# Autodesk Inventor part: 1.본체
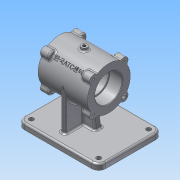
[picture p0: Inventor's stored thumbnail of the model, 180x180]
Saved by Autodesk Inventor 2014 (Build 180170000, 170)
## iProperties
Created: 2016-01
Part Number: 1.본체
Material: 알루미늄 6061
Document SubType Name: Modeling
Designer: Administrator
Density: 2.71 g/cm^3
Appearance: 알루미늄 - 평지
Mass: 1060.55 g
Surface Area: 842.535 cm^2
Volume: 391.348 cm^3
Author: Administrator
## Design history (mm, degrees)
sketch "스케치1"
  geometry: L1 (-70, 55)-(70, 55); L2 (70, 55)-(70, -55); L3 (70, -55)-(-70, -55); L4 (-70, -55)-(-70, 55); L5 (-70, 55)-(70, -55); L6 (70, 55)-(-70, -55); 1 further point
  constraints: 12 end point, 2 midpoint, 2 parallel, 1 horizontal, 1 perpendicular
  dimensions: "d0" = 140 distance between parallel lines of L2 L4; "d1" = 110 distance between parallel lines of L3 L1
extrude "돌출1" new body sketch "스케치1" distance "d2" = 10; taper "d3" = 0 deg
node "작업 평면1"
sketch "스케치2"
  geometry: L1 (0, 110)-(0, 0) reference; C1 r 37 at (-80, 55); 2 further points
  constraints: 1 centre point, 1 horizontal alignment, 1 midpoint
  dimensions: "d5" = 80 distance from line of L1 C1.centre; "d6" = 74 diameter of C1
extrude "돌출2" join sketch "스케치2" stored distance "d7" = 85; taper "d8" = 0 deg
node "작업 평면2"
sketch "스케치3"
  geometry: L1 (80, -55)-(80, 55) reference; L2 (80, -55)-(70, -55) reference; L3 (70, 55)-(70, -55) reference; L4 (80, 55)-(70, 55) reference; L5 (0, -37)-(70, -37); L6 (0, 37)-(70, 37); A1 r 37 centre (0, 0) between (0, -37) and (0, 37) reference; 1 further point
  constraints: 4 end point, 2 horizontal, 2 point on circle, 2 point on line, 2 tangent
extrude "돌출3" join sketch "스케치3" stored distance "d10" = 8; taper "d11" = 0 deg
node "작업 평면3"
sketch "스케치4"
  geometry: L1 (-70, 0)-(70, 0) reference; L2 (-70, 0)-(-70, 10) reference; L3 (70, 10)-(-70, 10) reference; L4 (70, 0)-(70, 10) reference; L5 (14, 80)-(14, 80) reference; L6 (14, 80)-(6, 80) reference; L7 (6, 80)-(6, 80) reference; L8 (14, 80)-(6, 80) reference; L9 (52.5, 43)-(52.5, 117) reference; L10 (-32.5, 117)-(-32.5, 43) reference; L11 (-9.782, 42.948)-(-15, 10); L12 (29.782, 42.948)-(35, 10); L13 (6, 10)-(14, 10) reference; L14 (6, 80)-(6, 10) reference; L15 (14, 80)-(6, 80) reference; L16 (14, 10)-(14, 80) reference; L17 (-9.782, 42.948)-(-6.179, 65.693); L18 (29.782, 42.948)-(26.179, 65.693); L19 (26.179, 65.693)-(-6.179, 65.693); 3 further points
  constraints: 10 end point, 2 collinear, 2 midpoint, 2 point on line, 1 equal length, 1 horizontal, 1 vertical alignment
  dimensions: "d13" = 99 deg angle of L3 L11; "d14" = 99 deg angle of L3 L12; "d18" = 25 distance of point (10, 10) L11.end; "d19" = 25 distance of point (10, 10) L12.end; "d20" = 32.35825 distance of L18.end L17.end
extrude "돌출4" join sketch "스케치4" stored distance "d21" = 12; taper "d22" = 0 deg
node "작업 평면4"
sketch "스케치6"
  geometry: C1 r 37 at (0, 0) reference; C2 r 23.5 at (0, 0); 1 further point
  constraints: 1 centre point, 1 coincident
  dimensions: "d24" = 47 diameter of C2
extrude "돌출5" cut sketch "스케치6" distance "d25" = 22; taper "d26" = 0 deg
sketch "스케치7"
  geometry: C1 r 21 at (0, 0); C2 r 37 at (0, 0) reference; 1 further point
  constraints: 1 centre point, 1 coincident, 1 horizontal alignment
  dimensions: "d27" = 42 diameter of C1
extrude "돌출6" cut sketch "스케치7" distance "d28" = 41; taper "d29" = 0 deg
node "작업 평면5"
sketch "스케치8"
  geometry: C1 r 37 at (0, 0) reference; C2 r 23.5 at (0, 0); 1 further point
  constraints: 1 centre point, 1 coincident
  dimensions: "d31" = 47 diameter of C2
extrude "돌출7" cut sketch "스케치8" distance "d32" = 22; taper "d33" = 0 deg
node "작업 평면6"
sketch "스케치9"
  geometry: L1 (32.5, -37)-(32.5, 37) reference; L2 (-52.5, 37)-(32.5, 37) reference; L3 (-52.5, 37)-(-52.5, -37) reference; L4 (-52.5, -37)-(32.5, -37) reference; C1 r 5 at (-10, 0); 2 further points
  constraints: 1 centre point, 1 horizontal alignment, 1 midpoint
  dimensions: "d35" = 42.5 distance from line of C1.centre L3; "d36" = 10 diameter of C1
extrude "돌출8" join sketch "스케치9" stored distance "d37" = 22; taper "d38" = 0 deg
sketch "스케치10"
  geometry: L1 (-52.5, 37)-(-52.5, -37) reference; 1 further point
hole "구멍1" diameter "d42" = 5.188; stored, may be unused: countersink angle "d46" = 90 deg, drill point angle "d48" = 0 deg; dims "d40" = 10, "d41" = 10, "d43" = 10, "d44" = 10, "d45" = 2, "d47" = 8
sketch "스케치11"
  geometry: C1 r 23.5 at (0, 0) reference; C2 r 7 at (-26.163, -26.163); C3 r 7 at (-26.163, 26.163); C4 r 7 at (26.163, -26.163); C5 r 7 at (26.163, 26.163); A1 r 37 centre (0, 0) between (-26.163, -26.163) and (-26.163, 26.163) reference; A2 r 37 centre (0, 0) between (-26.163, -26.163) and (-26.163, 26.163); 2 further points
  constraints: 8 point on circle, 5 centre point, 4 equal radius, 2 coincident, 2 horizontal alignment, 2 vertical alignment
  dimensions: "d49" = 7 radius of C3; "d50" = 90 deg dimension on C1.centre C3.centre C2.centre
extrude "돌출9" join sketch "스케치11" distance "d51" = 15; taper "d52" = 0 deg
sketch "스케치12"
  geometry: A1 r 7 centre (-106.163, 81.163) between (-100.767, 85.622) and (-110.622, 75.767) reference; A2 r 7 centre (-106.163, 28.837) between (-110.622, 34.233) and (-100.767, 24.378) reference; A3 r 7 centre (-53.837, 28.837) between (-59.233, 24.378) and (-49.378, 34.233) reference; A4 r 7 centre (-53.837, 81.163) between (-49.378, 75.767) and (-59.233, 85.622) reference; 5 further points
  constraints: 4 coincident
hole "구멍2" sketch "스케치12" at (-106.163, 81.163), (-106.163, 28.837), (-53.837, 28.837), (-53.837, 81.163) diameter "d53" = 3.242; stored, may be unused: countersink angle "d57" = 90 deg, drill point angle "d59" = 118 deg; dims "d54" = 9, "d55" = 10, "d56" = 2, "d58" = 11
node "작업 평면7"
sketch "스케치13"
  geometry: L1 (70, 55)-(-70, 55) reference; L2 (-70, 55)-(-70, -55) reference; L3 (-58, 43)-(58, 43); L4 (58, 43)-(58, -43); L5 (58, -43)-(-58, -43); L6 (-58, -43)-(-58, 43); 5 further points
  constraints: 8 end point, 4 coincident, 2 parallel, 1 horizontal, 1 perpendicular
  dimensions: "d61" = 86 distance between parallel lines of L5 L3; "d62" = 116 distance between parallel lines of L4 L6; "d63" = 12 distance from line of point (-58, 43) L1; "d64" = 12 distance from line of L2 point (-58, 43)
hole "구멍3" sketch "스케치13" at (-58, 43), (58, 43), (-58, -43), (58, -43) diameter "d65" = 8; stored, may be unused: countersink angle "d69" = 90 deg, drill point angle "d71" = 118 deg; dims "d66" = 9, "d67" = 10, "d68" = 2, "d70" = 11
sketch "스케치14"
  geometry: L1 (70, 55)-(-70, 55) reference; L2 (70, -55)-(70, 55) reference; L3 (-35, 40)-(38.226, 40); L4 (55, 23.226)-(55, -23.226); L5 (38.226, -40)-(-38.226, -40); L6 (-55, -23.226)-(-55, 23.226); L7 (-55, 40)-(55, -40); L8 (55, 40)-(-55, -40); C1 r 4 at (58, -43) reference; C2 r 4 at (58, 43) reference; C3 r 4 at (-58, 43) reference; C4 r 4 at (-58, -43) reference; A1 r 20 centre (-58, -43) between (-38.226, -40) and (-55, -23.226); A2 r 20 centre (58, -43) between (55, -23.226) and (38.226, -40); A3 r 20 centre (58, 43) between (38.226, 40) and (55, 23.226); A4 r 20 centre (-58, 43) between (-55, 23.226) and (-38.278, 39.677); A5 r 16.774 centre (38.226, 23.226) between (55, 23.226) and (55, 23.226); A6 r 16.774 centre (38.226, 23.226) between (38.226, 40) and (38.226, 40); A7 r 16.774 centre (38.226, -23.226) between (38.226, -40) and (38.226, -40); A8 r 16.774 centre (38.226, -23.226) between (55, -23.226) and (55, -23.226); A9 r 16.774 centre (-35, 23.226) between (-35, 40) and (-38.278, 39.677); A10 r 20 centre (-35, 23.226) between (-55, 23.226) and (-55, 23.226); A11 r 16.774 centre (-38.226, -23.226) between (-55, -23.226) and (-55, -23.226); A12 r 16.774 centre (-38.226, -23.226) between (-38.226, -40) and (-38.226, -40); 8 further points
  constraints: 37 point on circle, 12 centre point, 12 end point, 9 point on line, 8 tangent, 4 coincident, 3 equal radius, 2 midpoint, 2 parallel, 1 horizontal, 1 perpendicular
  dimensions: "d73" = 15 distance between parallel lines of L4 L2; "d74" = 15 distance between parallel lines of L1 L3; "d77" = 20 radius of A4
extrude "돌출10" cut sketch "스케치14" distance "d78" = 5; taper "d79" = 0 deg
sketch "스케치15"
  geometry: L1 (-80, 55)-(-106.163, 28.837); L2 (-106.163, 28.837)-(-136.752, -1.752); C1 r 1.621 at (-53.837, 28.837) reference; C2 r 1.621 at (-106.163, 81.163) reference; C3 r 1.621 at (-106.163, 28.837) reference; C4 r 1.621 at (-53.837, 81.163) reference; C5 r 23.5 at (-80, 55) reference; A1 r 37 centre (-80, 55) between (-59.233, 85.622) and (-100.767, 85.622) reference; A2 r 7 centre (-106.163, 81.163) between (-100.767, 85.622) and (-110.622, 75.767) reference; A3 r 37 centre (-80, 55) between (-110.622, 75.767) and (-110.622, 34.233) reference; A4 r 7 centre (-106.163, 28.837) between (-110.622, 34.233) and (-100.767, 24.378) reference; A5 r 37 centre (-80, 55) between (-100.767, 24.378) and (-59.233, 24.378) reference; A6 r 7 centre (-53.837, 28.837) between (-59.233, 24.378) and (-49.378, 34.233) reference; A7 r 37 centre (-80, 55) between (-49.378, 34.233) and (-49.378, 75.767) reference; A8 r 7 centre (-53.837, 81.163) between (-49.378, 75.767) and (-59.233, 85.622) reference; 3 further points
  constraints: 4 end point, 1 coincident, 1 collinear, 1 point on circle
node "작업 평면9"
sketch "스케치16"
  geometry: L1 (0, 7)-(0, -7) reference; L2 (-46.5, 26.163)-(-38.5, 26.163) reference; 8 further points
  constraints: 2 horizontal alignment, 2 midpoint, 2 vertical alignment, 1 other
fillet "모깎기1" dims "d80" = 12, "d82" = 0.3
fillet "모깎기2" dims "d81" = 1
fillet "모깎기3" dims "d83" = 3
fillet "모깎기4" dims "d84" = 3
feature "엠보싱1" dims "d85" = 0.5, "d86" = 0
fillet "모깎기5" dims "d87" = 3
fillet "모깎기6" dims "d88" = 3
fillet "모깎기7" dims "d89" = 3
chamfer "모따기1" distance "d90" = 1; stored, may be unused: second distance "d91" = 2, angle "d92" = 45 deg
fillet "모깎기8" dims "d93" = 3
node "솔리드1"
mirror "대칭1"
node "투영된 루프1"
node "투영된 루프2"
node "투영된 루프3"
node "투영된 루프4"
node "투영된 루프5"
other parameters: "d9" = -42.5, "d12" = 0, "d23" = -22, "d30" = -22, "d34" = 122, "d60" = -42.5
